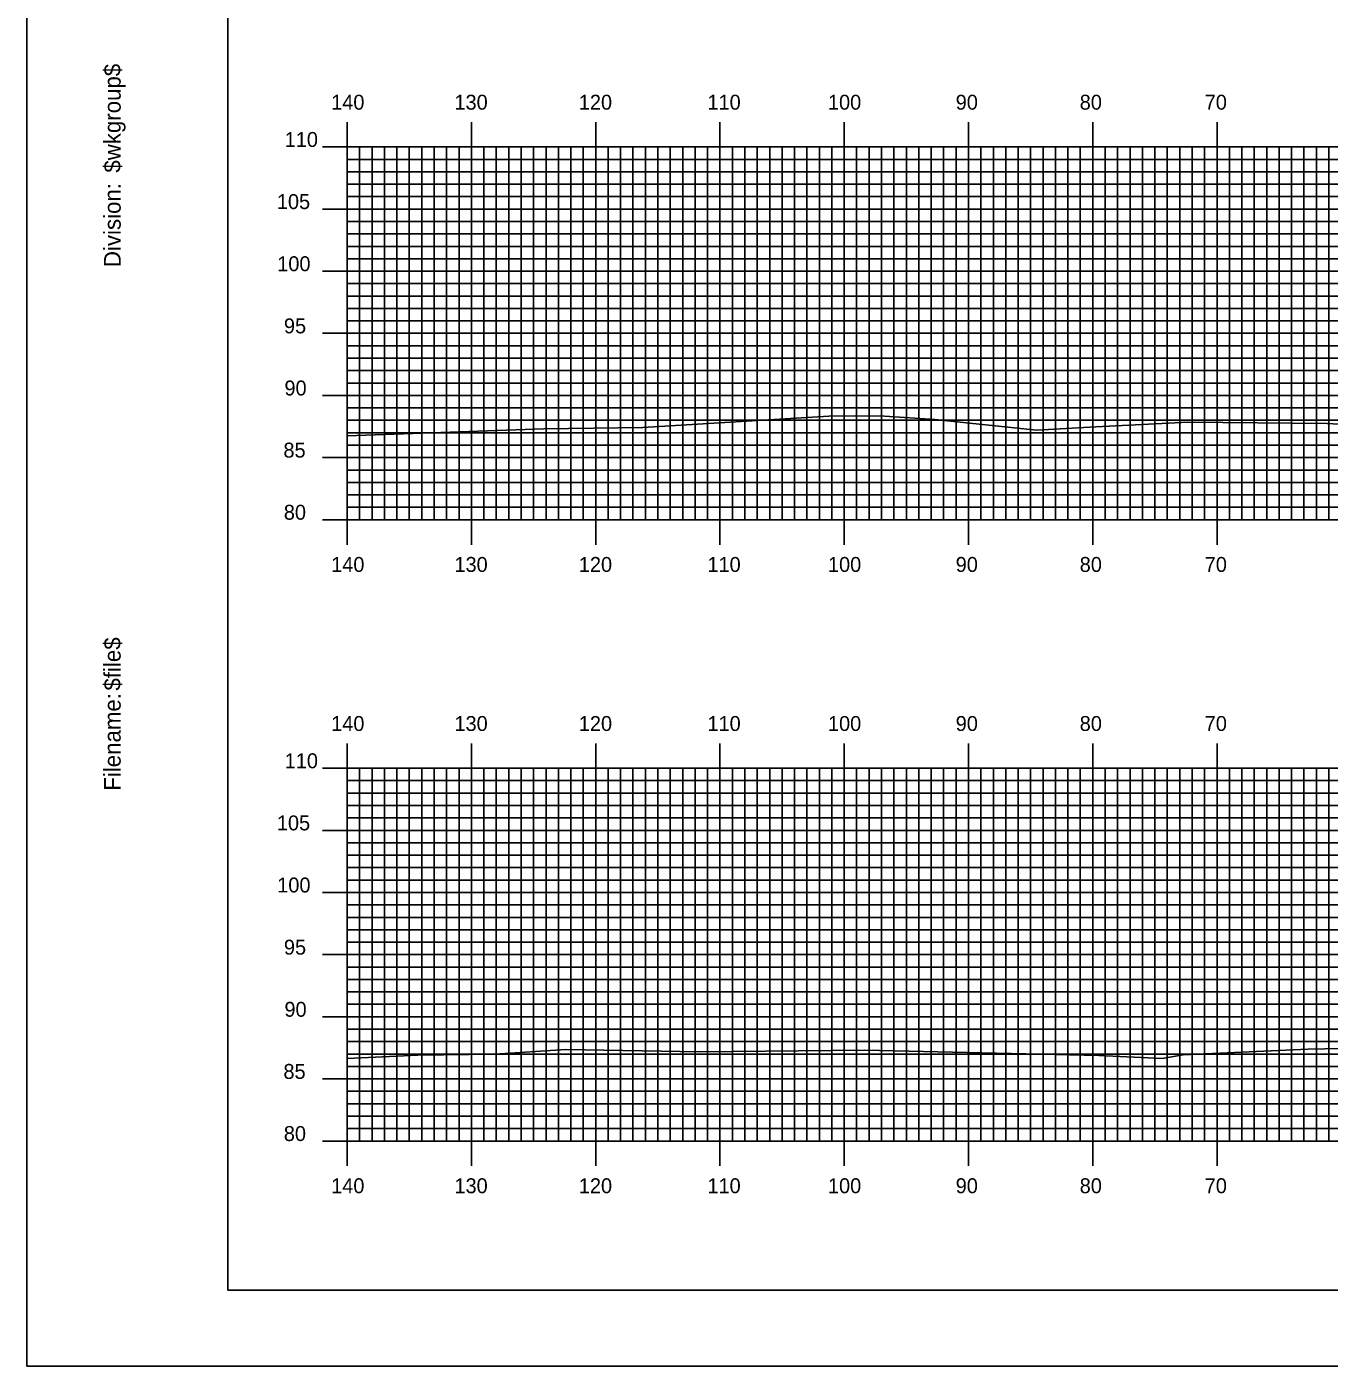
# Model space of a CAD drawing. Extents: x 1762972 to 1763315, y 442591 to 442811.
# Drawn here: x 1762971.5 to 1763076.3, y 442590.5 to 442698.3 of the extents above; entities that cross this region are included whole.
import ezdxf

# ---------------------------------------------------------------- set-up
doc = ezdxf.new("R2010")
doc.units = 0
for name, color, linetype in [('BORDER', 7, 'Continuous'), ('H_V ANNOTATION', 7, 'Continuous'), ('MAJOR', 7, 'Continuous'), ('MINOR', 7, 'Continuous'), ('PLOT BOUNDARY', 7, 'Continuous'), ('S_Roadway_Centerline', 7, 'Continuous')]:
    doc.layers.add(name, color=color, linetype=linetype)

msp = doc.modelspace()

# ---------------------------------------------------------------- linework, layer by layer
at = {"layer": 'BORDER'}
msp.add_lwpolyline([(1762987.69, 442596.67), (1763307.69, 442596.67), (1763307.69, 442806.67), (1762987.69, 442806.67)], close=True, dxfattribs=at)
at = {"layer": 'MAJOR'}
for p, q in [((1762997.29, 442690.67), (1762997.29, 442688.67)), ((1763007.29, 442690.67), (1763007.29, 442688.67)), ((1763017.29, 442690.67), (1763017.29, 442688.67)), ((1763027.29, 442690.67), (1763027.29, 442688.67)), ((1763037.29, 442690.67), (1763037.29, 442688.67)), ((1763047.29, 442690.67), (1763047.29, 442688.67)), ((1763057.29, 442690.67), (1763057.29, 442688.67)), ((1763067.29, 442690.67), (1763067.29, 442688.67)), ((1762995.29, 442688.67), (1762997.29, 442688.67)), ((1762997.29, 442688.67), (1763277.29, 442688.67)), ((1762997.29, 442658.67), (1762997.29, 442688.67)), ((1762997.29, 442658.67), (1762997.29, 442688.67)), ((1762997.29, 442688.67), (1763277.29, 442688.67)), ((1763007.29, 442658.67), (1763007.29, 442688.67)), ((1763017.29, 442658.67), (1763017.29, 442688.67)), ((1763027.29, 442658.67), (1763027.29, 442688.67)), ((1763037.29, 442658.67), (1763037.29, 442688.67)), ((1763047.29, 442658.67), (1763047.29, 442688.67)), ((1763057.29, 442658.67), (1763057.29, 442688.67)), ((1763067.29, 442658.67), (1763067.29, 442688.67)), ((1762995.29, 442683.67), (1762997.29, 442683.67)), ((1762997.29, 442683.67), (1763277.29, 442683.67)), ((1762995.29, 442678.67), (1762997.29, 442678.67)), ((1762997.29, 442678.67), (1763277.29, 442678.67)), ((1762995.29, 442673.67), (1762997.29, 442673.67)), ((1762997.29, 442673.67), (1763277.29, 442673.67)), ((1762995.29, 442668.67), (1762997.29, 442668.67)), ((1762997.29, 442668.67), (1763277.29, 442668.67)), ((1762995.29, 442663.67), (1762997.29, 442663.67)), ((1762997.29, 442663.67), (1763277.29, 442663.67)), ((1762995.29, 442658.67), (1762997.29, 442658.67)), ((1762997.29, 442658.67), (1763277.29, 442658.67)), ((1762997.29, 442658.67), (1763277.29, 442658.67)), ((1762997.29, 442656.66), (1762997.29, 442658.67)), ((1763007.29, 442656.66), (1763007.29, 442658.67)), ((1763017.29, 442656.66), (1763017.29, 442658.67)), ((1763027.29, 442656.66), (1763027.29, 442658.67)), ((1763037.29, 442656.66), (1763037.29, 442658.67)), ((1763047.29, 442656.66), (1763047.29, 442658.67)), ((1763057.29, 442656.66), (1763057.29, 442658.67)), ((1763067.29, 442656.66), (1763067.29, 442658.67)), ((1762997.29, 442640.67), (1762997.29, 442638.67)), ((1763007.29, 442640.67), (1763007.29, 442638.67)), ((1763017.29, 442640.67), (1763017.29, 442638.67)), ((1763027.29, 442640.67), (1763027.29, 442638.67)), ((1763037.29, 442640.67), (1763037.29, 442638.67)), ((1763047.29, 442640.67), (1763047.29, 442638.67)), ((1763057.29, 442640.67), (1763057.29, 442638.67)), ((1763067.29, 442640.67), (1763067.29, 442638.67)), ((1762995.29, 442638.67), (1762997.29, 442638.67)), ((1762997.29, 442638.67), (1763277.29, 442638.67)), ((1762997.29, 442608.67), (1762997.29, 442638.67)), ((1762997.29, 442608.67), (1762997.29, 442638.67)), ((1762997.29, 442638.67), (1763277.29, 442638.67)), ((1763007.29, 442608.67), (1763007.29, 442638.67)), ((1763017.29, 442608.67), (1763017.29, 442638.67)), ((1763027.29, 442608.67), (1763027.29, 442638.67)), ((1763037.29, 442608.67), (1763037.29, 442638.67)), ((1763047.29, 442608.67), (1763047.29, 442638.67)), ((1763057.29, 442608.67), (1763057.29, 442638.67)), ((1763067.29, 442608.67), (1763067.29, 442638.67)), ((1762995.29, 442633.67), (1762997.29, 442633.67)), ((1762997.29, 442633.67), (1763277.29, 442633.67)), ((1762995.29, 442628.67), (1762997.29, 442628.67)), ((1762997.29, 442628.67), (1763277.29, 442628.67)), ((1762995.29, 442623.67), (1762997.29, 442623.67)), ((1762997.29, 442623.67), (1763277.29, 442623.67)), ((1762995.29, 442618.67), (1762997.29, 442618.67)), ((1762997.29, 442618.67), (1763277.29, 442618.67)), ((1762995.29, 442613.67), (1762997.29, 442613.67)), ((1762997.29, 442613.67), (1763277.29, 442613.67)), ((1762995.29, 442608.67), (1762997.29, 442608.67)), ((1762997.29, 442608.67), (1763277.29, 442608.67)), ((1762997.29, 442608.67), (1763277.29, 442608.67)), ((1762997.29, 442606.66), (1762997.29, 442608.67)), ((1763007.29, 442606.66), (1763007.29, 442608.67)), ((1763017.29, 442606.66), (1763017.29, 442608.67)), ((1763027.29, 442606.66), (1763027.29, 442608.67)), ((1763037.29, 442606.66), (1763037.29, 442608.67)), ((1763047.29, 442606.66), (1763047.29, 442608.67)), ((1763057.29, 442606.66), (1763057.29, 442608.67)), ((1763067.29, 442606.66), (1763067.29, 442608.67))]:
    msp.add_line(p, q, dxfattribs=at)
at = {"layer": 'MINOR'}
for p, q in [((1762998.29, 442658.67), (1762998.29, 442688.67)), ((1762999.29, 442658.67), (1762999.29, 442688.67)), ((1763000.29, 442658.67), (1763000.29, 442688.67)), ((1763001.29, 442658.67), (1763001.29, 442688.67)), ((1763002.29, 442658.67), (1763002.29, 442688.67)), ((1763003.29, 442658.67), (1763003.29, 442688.67)), ((1763004.29, 442658.67), (1763004.29, 442688.67)), ((1763005.29, 442658.67), (1763005.29, 442688.67)), ((1763006.29, 442658.67), (1763006.29, 442688.67)), ((1763008.29, 442658.67), (1763008.29, 442688.67)), ((1763009.29, 442658.67), (1763009.29, 442688.67)), ((1763010.29, 442658.67), (1763010.29, 442688.67)), ((1763011.29, 442658.67), (1763011.29, 442688.67)), ((1763012.29, 442658.67), (1763012.29, 442688.67)), ((1763013.29, 442658.67), (1763013.29, 442688.67)), ((1763014.29, 442658.67), (1763014.29, 442688.67)), ((1763015.29, 442658.67), (1763015.29, 442688.67)), ((1763016.29, 442658.67), (1763016.29, 442688.67)), ((1763018.29, 442658.67), (1763018.29, 442688.67)), ((1763019.29, 442658.67), (1763019.29, 442688.67)), ((1763020.29, 442658.67), (1763020.29, 442688.67)), ((1763021.29, 442658.67), (1763021.29, 442688.67)), ((1763022.29, 442658.67), (1763022.29, 442688.67)), ((1763023.29, 442658.67), (1763023.29, 442688.67)), ((1763024.29, 442658.67), (1763024.29, 442688.67)), ((1763025.29, 442658.67), (1763025.29, 442688.67)), ((1763026.29, 442658.67), (1763026.29, 442688.67)), ((1763028.29, 442658.67), (1763028.29, 442688.67)), ((1763029.29, 442658.67), (1763029.29, 442688.67)), ((1763030.29, 442658.67), (1763030.29, 442688.67)), ((1763031.29, 442658.67), (1763031.29, 442688.67)), ((1763032.29, 442658.67), (1763032.29, 442688.67)), ((1763033.29, 442658.67), (1763033.29, 442688.67)), ((1763034.29, 442658.67), (1763034.29, 442688.67)), ((1763035.29, 442658.67), (1763035.29, 442688.67)), ((1763036.29, 442658.67), (1763036.29, 442688.67)), ((1763038.29, 442658.67), (1763038.29, 442688.67)), ((1763039.29, 442658.67), (1763039.29, 442688.67)), ((1763040.29, 442658.67), (1763040.29, 442688.67)), ((1763041.29, 442658.67), (1763041.29, 442688.67)), ((1763042.29, 442658.67), (1763042.29, 442688.67)), ((1763043.29, 442658.67), (1763043.29, 442688.67)), ((1763044.29, 442658.67), (1763044.29, 442688.67)), ((1763045.29, 442658.67), (1763045.29, 442688.67)), ((1763046.29, 442658.67), (1763046.29, 442688.67)), ((1763048.29, 442658.67), (1763048.29, 442688.67)), ((1763049.29, 442658.67), (1763049.29, 442688.67)), ((1763050.29, 442658.67), (1763050.29, 442688.67)), ((1763051.29, 442658.67), (1763051.29, 442688.67)), ((1763052.29, 442658.67), (1763052.29, 442688.67)), ((1763053.29, 442658.67), (1763053.29, 442688.67)), ((1763054.29, 442658.67), (1763054.29, 442688.67)), ((1763055.29, 442658.67), (1763055.29, 442688.67)), ((1763056.29, 442658.67), (1763056.29, 442688.67)), ((1763058.29, 442658.67), (1763058.29, 442688.67)), ((1763059.29, 442658.67), (1763059.29, 442688.67)), ((1763060.29, 442658.67), (1763060.29, 442688.67)), ((1763061.29, 442658.67), (1763061.29, 442688.67)), ((1763062.29, 442658.67), (1763062.29, 442688.67)), ((1763063.29, 442658.67), (1763063.29, 442688.67)), ((1763064.29, 442658.67), (1763064.29, 442688.67)), ((1763065.29, 442658.67), (1763065.29, 442688.67)), ((1763066.29, 442658.67), (1763066.29, 442688.67)), ((1763068.29, 442658.67), (1763068.29, 442688.67)), ((1763069.29, 442658.67), (1763069.29, 442688.67)), ((1763070.29, 442658.67), (1763070.29, 442688.67)), ((1763071.29, 442658.67), (1763071.29, 442688.67)), ((1763072.29, 442658.67), (1763072.29, 442688.67)), ((1763073.29, 442658.67), (1763073.29, 442688.67)), ((1763074.29, 442658.67), (1763074.29, 442688.67)), ((1763075.29, 442658.67), (1763075.29, 442688.67)), ((1763076.29, 442658.67), (1763076.29, 442688.67)), ((1762997.29, 442687.67), (1763277.29, 442687.67)), ((1762997.29, 442687.67), (1762999.3, 442687.67)), ((1762997.29, 442686.67), (1763277.29, 442686.67)), ((1762997.29, 442686.67), (1762999.3, 442686.67)), ((1762997.29, 442685.67), (1763277.29, 442685.67)), ((1762997.29, 442685.67), (1762999.3, 442685.67)), ((1762997.29, 442684.67), (1763277.29, 442684.67)), ((1762997.29, 442684.67), (1762999.3, 442684.67)), ((1762997.29, 442682.67), (1763277.29, 442682.67)), ((1762997.29, 442682.67), (1762999.3, 442682.67)), ((1762997.29, 442681.67), (1763277.29, 442681.67)), ((1762997.29, 442681.67), (1762999.3, 442681.67)), ((1762997.29, 442680.67), (1763277.29, 442680.67)), ((1762997.29, 442680.67), (1762999.3, 442680.67)), ((1762997.29, 442679.67), (1763277.29, 442679.67)), ((1762997.29, 442679.67), (1762999.3, 442679.67)), ((1762997.29, 442677.67), (1763277.29, 442677.67)), ((1762997.29, 442677.67), (1762999.3, 442677.67)), ((1762997.29, 442676.67), (1763277.29, 442676.67)), ((1762997.29, 442676.67), (1762999.3, 442676.67)), ((1762997.29, 442675.67), (1763277.29, 442675.67)), ((1762997.29, 442675.67), (1762999.3, 442675.67)), ((1762997.29, 442674.67), (1763277.29, 442674.67)), ((1762997.29, 442674.67), (1762999.3, 442674.67)), ((1762997.29, 442672.67), (1763277.29, 442672.67)), ((1762997.29, 442672.67), (1762999.3, 442672.67)), ((1762997.29, 442671.67), (1763277.29, 442671.67)), ((1762997.29, 442671.67), (1762999.3, 442671.67)), ((1762997.29, 442670.67), (1763277.29, 442670.67)), ((1762997.29, 442670.67), (1762999.3, 442670.67)), ((1762997.29, 442669.67), (1763277.29, 442669.67)), ((1762997.29, 442669.67), (1762999.3, 442669.67)), ((1762997.29, 442667.67), (1763277.29, 442667.67)), ((1762997.29, 442667.67), (1762999.3, 442667.67)), ((1762997.29, 442666.67), (1763277.29, 442666.67)), ((1762997.29, 442666.67), (1762999.3, 442666.67)), ((1762997.29, 442665.67), (1763277.29, 442665.67)), ((1762997.29, 442665.67), (1762999.3, 442665.67)), ((1762997.29, 442664.67), (1763277.29, 442664.67)), ((1762997.29, 442664.67), (1762999.3, 442664.67)), ((1762997.29, 442662.67), (1763277.29, 442662.67)), ((1762997.29, 442662.67), (1762999.3, 442662.67)), ((1762997.29, 442661.67), (1763277.29, 442661.67)), ((1762997.29, 442661.67), (1762999.3, 442661.67)), ((1762997.29, 442660.67), (1763277.29, 442660.67)), ((1762997.29, 442660.67), (1762999.3, 442660.67)), ((1762997.29, 442659.67), (1763277.29, 442659.67)), ((1762997.29, 442659.67), (1762999.3, 442659.67)), ((1762998.29, 442608.67), (1762998.29, 442638.67)), ((1762999.29, 442608.67), (1762999.29, 442638.67)), ((1763000.29, 442608.67), (1763000.29, 442638.67)), ((1763001.29, 442608.67), (1763001.29, 442638.67)), ((1763002.29, 442608.67), (1763002.29, 442638.67)), ((1763003.29, 442608.67), (1763003.29, 442638.67)), ((1763004.29, 442608.67), (1763004.29, 442638.67)), ((1763005.29, 442608.67), (1763005.29, 442638.67)), ((1763006.29, 442608.67), (1763006.29, 442638.67)), ((1763008.29, 442608.67), (1763008.29, 442638.67)), ((1763009.29, 442608.67), (1763009.29, 442638.67)), ((1763010.29, 442608.67), (1763010.29, 442638.67)), ((1763011.29, 442608.67), (1763011.29, 442638.67)), ((1763012.29, 442608.67), (1763012.29, 442638.67)), ((1763013.29, 442608.67), (1763013.29, 442638.67)), ((1763014.29, 442608.67), (1763014.29, 442638.67)), ((1763015.29, 442608.67), (1763015.29, 442638.67)), ((1763016.29, 442608.67), (1763016.29, 442638.67)), ((1763018.29, 442608.67), (1763018.29, 442638.67)), ((1763019.29, 442608.67), (1763019.29, 442638.67)), ((1763020.29, 442608.67), (1763020.29, 442638.67)), ((1763021.29, 442608.67), (1763021.29, 442638.67)), ((1763022.29, 442608.67), (1763022.29, 442638.67)), ((1763023.29, 442608.67), (1763023.29, 442638.67)), ((1763024.29, 442608.67), (1763024.29, 442638.67)), ((1763025.29, 442608.67), (1763025.29, 442638.67)), ((1763026.29, 442608.67), (1763026.29, 442638.67)), ((1763028.29, 442608.67), (1763028.29, 442638.67)), ((1763029.29, 442608.67), (1763029.29, 442638.67)), ((1763030.29, 442608.67), (1763030.29, 442638.67)), ((1763031.29, 442608.67), (1763031.29, 442638.67)), ((1763032.29, 442608.67), (1763032.29, 442638.67)), ((1763033.29, 442608.67), (1763033.29, 442638.67)), ((1763034.29, 442608.67), (1763034.29, 442638.67)), ((1763035.29, 442608.67), (1763035.29, 442638.67)), ((1763036.29, 442608.67), (1763036.29, 442638.67)), ((1763038.29, 442608.67), (1763038.29, 442638.67)), ((1763039.29, 442608.67), (1763039.29, 442638.67)), ((1763040.29, 442608.67), (1763040.29, 442638.67)), ((1763041.29, 442608.67), (1763041.29, 442638.67)), ((1763042.29, 442608.67), (1763042.29, 442638.67)), ((1763043.29, 442608.67), (1763043.29, 442638.67)), ((1763044.29, 442608.67), (1763044.29, 442638.67)), ((1763045.29, 442608.67), (1763045.29, 442638.67)), ((1763046.29, 442608.67), (1763046.29, 442638.67)), ((1763048.29, 442608.67), (1763048.29, 442638.67)), ((1763049.29, 442608.67), (1763049.29, 442638.67)), ((1763050.29, 442608.67), (1763050.29, 442638.67)), ((1763051.29, 442608.67), (1763051.29, 442638.67)), ((1763052.29, 442608.67), (1763052.29, 442638.67)), ((1763053.29, 442608.67), (1763053.29, 442638.67)), ((1763054.29, 442608.67), (1763054.29, 442638.67)), ((1763055.29, 442608.67), (1763055.29, 442638.67)), ((1763056.29, 442608.67), (1763056.29, 442638.67)), ((1763058.29, 442608.67), (1763058.29, 442638.67)), ((1763059.29, 442608.67), (1763059.29, 442638.67)), ((1763060.29, 442608.67), (1763060.29, 442638.67)), ((1763061.29, 442608.67), (1763061.29, 442638.67)), ((1763062.29, 442608.67), (1763062.29, 442638.67)), ((1763063.29, 442608.67), (1763063.29, 442638.67)), ((1763064.29, 442608.67), (1763064.29, 442638.67)), ((1763065.29, 442608.67), (1763065.29, 442638.67)), ((1763066.29, 442608.67), (1763066.29, 442638.67)), ((1763068.29, 442608.67), (1763068.29, 442638.67)), ((1763069.29, 442608.67), (1763069.29, 442638.67)), ((1763070.29, 442608.67), (1763070.29, 442638.67)), ((1763071.29, 442608.67), (1763071.29, 442638.67)), ((1763072.29, 442608.67), (1763072.29, 442638.67)), ((1763073.29, 442608.67), (1763073.29, 442638.67)), ((1763074.29, 442608.67), (1763074.29, 442638.67)), ((1763075.29, 442608.67), (1763075.29, 442638.67)), ((1763076.29, 442608.67), (1763076.29, 442638.67)), ((1762997.29, 442637.67), (1763277.29, 442637.67)), ((1762997.29, 442637.67), (1762999.3, 442637.67)), ((1762997.29, 442636.67), (1763277.29, 442636.67)), ((1762997.29, 442636.67), (1762999.3, 442636.67)), ((1762997.29, 442635.67), (1763277.29, 442635.67)), ((1762997.29, 442635.67), (1762999.3, 442635.67)), ((1762997.29, 442634.67), (1763277.29, 442634.67)), ((1762997.29, 442634.67), (1762999.3, 442634.67)), ((1762997.29, 442632.67), (1763277.29, 442632.67)), ((1762997.29, 442632.67), (1762999.3, 442632.67)), ((1762997.29, 442631.67), (1763277.29, 442631.67)), ((1762997.29, 442631.67), (1762999.3, 442631.67)), ((1762997.29, 442630.67), (1763277.29, 442630.67)), ((1762997.29, 442630.67), (1762999.3, 442630.67)), ((1762997.29, 442629.67), (1763277.29, 442629.67)), ((1762997.29, 442629.67), (1762999.3, 442629.67)), ((1762997.29, 442627.67), (1763277.29, 442627.67)), ((1762997.29, 442627.67), (1762999.3, 442627.67)), ((1762997.29, 442626.67), (1763277.29, 442626.67)), ((1762997.29, 442626.67), (1762999.3, 442626.67)), ((1762997.29, 442625.67), (1763277.29, 442625.67)), ((1762997.29, 442625.67), (1762999.3, 442625.67)), ((1762997.29, 442624.67), (1763277.29, 442624.67)), ((1762997.29, 442624.67), (1762999.3, 442624.67)), ((1762997.29, 442622.67), (1763277.29, 442622.67)), ((1762997.29, 442622.67), (1762999.3, 442622.67)), ((1762997.29, 442621.67), (1763277.29, 442621.67)), ((1762997.29, 442621.67), (1762999.3, 442621.67)), ((1762997.29, 442620.67), (1763277.29, 442620.67)), ((1762997.29, 442620.67), (1762999.3, 442620.67)), ((1762997.29, 442619.67), (1763277.29, 442619.67)), ((1762997.29, 442619.67), (1762999.3, 442619.67)), ((1762997.29, 442617.67), (1763277.29, 442617.67)), ((1762997.29, 442617.67), (1762999.3, 442617.67)), ((1762997.29, 442616.67), (1763277.29, 442616.67)), ((1762997.29, 442616.67), (1762999.3, 442616.67)), ((1762997.29, 442615.67), (1763277.29, 442615.67)), ((1762997.29, 442615.67), (1762999.3, 442615.67)), ((1762997.29, 442614.67), (1763277.29, 442614.67)), ((1762997.29, 442614.67), (1762999.3, 442614.67)), ((1762997.29, 442612.67), (1763277.29, 442612.67)), ((1762997.29, 442612.67), (1762999.3, 442612.67)), ((1762997.29, 442611.67), (1763277.29, 442611.67)), ((1762997.29, 442611.67), (1762999.3, 442611.67)), ((1762997.29, 442610.67), (1763277.29, 442610.67)), ((1762997.29, 442610.67), (1762999.3, 442610.67)), ((1762997.29, 442609.67), (1763277.29, 442609.67)), ((1762997.29, 442609.67), (1762999.3, 442609.67))]:
    msp.add_line(p, q, dxfattribs=at)
at = {"layer": 'PLOT BOUNDARY'}
msp.add_lwpolyline([(1762971.51, 442590.55), (1763311.51, 442590.55), (1763311.51, 442810.55), (1762971.51, 442810.55)], close=True, dxfattribs=at)
at = {"layer": 'S_Roadway_Centerline'}
for points in [[(1762997.29, 442665.43), (1763013.11, 442665.98), (1763021.07, 442666.09), (1763036.04, 442666.99), (1763038.16, 442667.04), (1763040.53, 442666.99), (1763044.59, 442666.73), (1763052.77, 442665.87), (1763057.54, 442666.14), (1763064.98, 442666.52), (1763076.16, 442666.41), (1763077.6, 442666.34), (1763080.19, 442666.28), (1763113.21, 442665.36), (1763114.75, 442665.44), (1763125.83, 442665.97), (1763131.53, 442666.32), (1763148.37, 442667.91), (1763150.54, 442668.16), (1763162.56, 442669.17), (1763168.92, 442669.48), (1763185.04, 442670.28), (1763188.37, 442670.4), (1763198.83, 442670.65)], [(1762997.29, 442615.3), (1763002.97, 442615.58), (1763009.16, 442615.66), (1763014.89, 442616.04), (1763025.62, 442615.84), (1763038.94, 442615.98), (1763057.77, 442615.54), (1763062.87, 442615.31), (1763064.56, 442615.61), (1763074.61, 442616.05), (1763085.57, 442616.27)]]:
    msp.add_lwpolyline(points, dxfattribs=at)

# ---------------------------------------------------------------- texts
at = {"layer": 'BORDER'}
for s, p in [('$wkgroup$', (1762979.06, 442686.6)), ('Division:', (1762979.06, 442679)), ('$file$', (1762979.06, 442644.92)), ('Filename:', (1762979.06, 442636.86))]:
    msp.add_text(s, height=1.339, rotation=90, dxfattribs=at).set_placement(p)
at = {"layer": 'H_V ANNOTATION'}
for s, p in [('140', (1762996, 442691.67)), ('130', (1763005.92, 442691.67)), ('120', (1763015.93, 442691.67)), ('110', (1763026.28, 442691.67)), ('100', (1763035.98, 442691.67)), ('90', (1763046.26, 442691.67)), ('80', (1763056.24, 442691.67)), ('70', (1763066.3, 442691.67)), ('110', (1762992.26, 442688.67)), ('105', (1762991.63, 442683.67)), ('100', (1762991.66, 442678.67)), ('95', (1762992.2, 442673.67)), ('90', (1762992.24, 442668.67)), ('85', (1762992.16, 442663.67)), ('80', (1762992.19, 442658.67)), ('140', (1762996, 442654.47)), ('130', (1763005.92, 442654.47)), ('120', (1763015.93, 442654.47)), ('110', (1763026.28, 442654.47)), ('100', (1763035.98, 442654.47)), ('90', (1763046.26, 442654.47)), ('80', (1763056.24, 442654.47)), ('70', (1763066.3, 442654.47)), ('140', (1762996, 442641.67)), ('130', (1763005.92, 442641.67)), ('120', (1763015.93, 442641.67)), ('110', (1763026.28, 442641.67)), ('100', (1763035.98, 442641.67)), ('90', (1763046.26, 442641.67)), ('80', (1763056.24, 442641.67)), ('70', (1763066.3, 442641.67)), ('110', (1762992.26, 442638.67)), ('105', (1762991.63, 442633.67)), ('100', (1762991.66, 442628.67)), ('95', (1762992.2, 442623.67)), ('90', (1762992.24, 442618.67)), ('85', (1762992.16, 442613.67)), ('80', (1762992.19, 442608.67)), ('140', (1762996, 442604.47)), ('130', (1763005.92, 442604.47)), ('120', (1763015.93, 442604.47)), ('110', (1763026.28, 442604.47)), ('100', (1763035.98, 442604.47)), ('90', (1763046.26, 442604.47)), ('80', (1763056.24, 442604.47)), ('70', (1763066.3, 442604.47))]:
    msp.add_text(s, height=1.2, dxfattribs=at).set_placement(p)
at = {"layer": 'MAJOR'}
for p in [(1762997.28, 442658.67), (1762997.28, 442608.67)]:
    msp.add_text('-', height=0.012, dxfattribs=at).set_placement(p)

doc.saveas('drawing.dxf')
